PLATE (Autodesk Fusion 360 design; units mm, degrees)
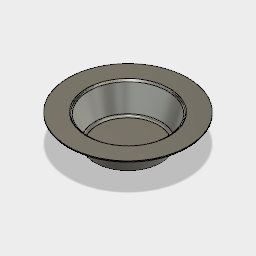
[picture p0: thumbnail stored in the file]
sketch "Sketch1"
  line L1 (66.5125, 0) -> (0, 0)
  line L2 (81.5125, 53) -> (66.5125, 0)
  line L3 (120, 53) -> (81.5125, 53)
  line L4 (120, 55) -> (120, 53)
  line L5 (0, 2) -> (0, 0)
  line L6 (65, 2) -> (0, 2)
  line L7 (80, 55) -> (65, 2)
  line L8 (120, 55) -> (80, 55)
  point P6 (120, 55)
  point P10 (80, 55)
  point P9 (65, 2)
  point P3 (66.5125, 0)
  point P7 (0, 0)
  point P8 (0, 2)
  point P5 (120, 53)
  dimension "d1" distance P6 P10 = 40
  dimension "d2" distance P9 P10 = 15
  dimension "d3" distance P3 P6 = 55
  dimension "d4" distance P7 P8 = 2
  dimension "d5" distance P5 P6 = 2
  dimension "d6" distance L2 L7 = 2
  dimension "d7" distance P8 P9 = 65
revolve "Revolve1" sketch "Sketch1" AlongAngle 360
fillet "Fillet1" radius 5
chamfer "Chamfer1" distance 3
